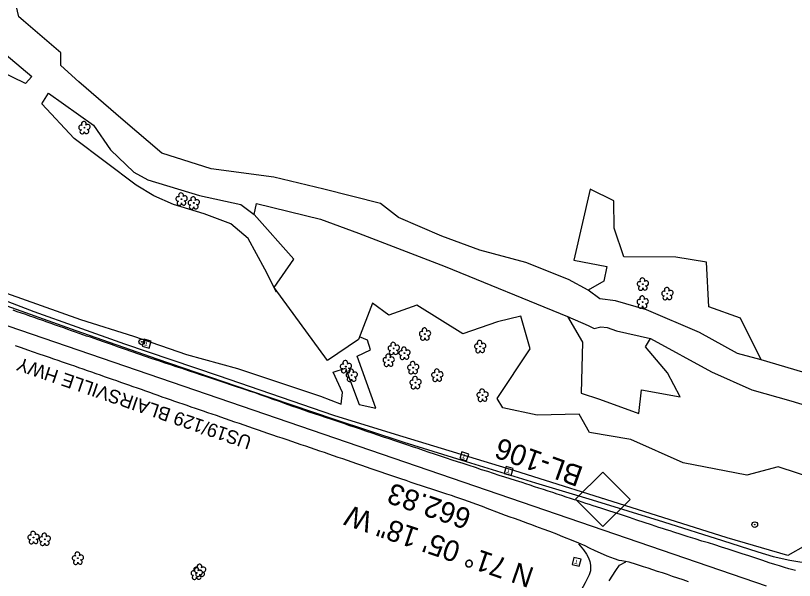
# Model space of a CAD drawing. Extents: x 478596 to 483012, y 490885 to 495165.
# Drawn here: x 479936 to 480534, y 493288 to 493722 of the extents above; entities that cross this region are included whole.
import ezdxf

# ---------------------------------------------------------------- set-up
doc = ezdxf.new("R2010")
doc.units = 0
for name, color, linetype in [('CTL Secondary Horizontal and Vertical CELL', 7, 'Continuous'), ('CTL Secondary Horizontal and Vertical Text', 7, 'Continuous'), ('Exist Guardrail', 7, 'Continuous'), ('Exist Horizontal Alignment', 7, 'Continuous'), ('Exist Horizontal Alignment Direction Label', 7, 'Continuous'), ('Exist Roads EOP', 7, 'Continuous'), ('Exist Roads EOP Text', 7, 'Continuous'), ('Exist Roads Soil', 7, 'Continuous'), ('Exist Utilities Other Located Object CELL', 7, 'Continuous'), ('Exist Utilities Telephone Pedestal CELL', 7, 'Continuous'), ('Exist Vegetation Hedge Row', 7, 'Continuous'), ('Exist Vegetation Tree CELL', 7, 'Continuous'), ('Exist Vegetation Woods Line', 7, 'Continuous')]:
    doc.layers.add(name, color=color, linetype=linetype)

msp = doc.modelspace()

# ---------------------------------------------------------------- linework, layer by layer
at = {"layer": 'CTL Secondary Horizontal and Vertical CELL'}
msp.add_line((480387.12, 493349.88), (480387.12, 493349.88), dxfattribs=at)
msp.add_lwpolyline([(480366.26, 493349.95), (480387.23, 493370.92), (480408.23, 493349.92), (480387.26, 493328.95)], close=True, dxfattribs=at)
at = {"layer": 'Exist Guardrail'}
msp.add_line((479896.1, 493510.36), (479982.05, 493479.53), dxfattribs=at)
for points in [[(479982.05, 493479.53), (480044.35, 493457.89), (480115.47, 493433.53), (480180.47, 493411.46), (480234.18, 493393.89), (480278.73, 493380.07), (480335.27, 493362.72), (480378.91, 493349.59), (480433.83, 493332.58), (480479.19, 493318.23)], [(480479.19, 493318.23), (480506.27, 493309.62), (480518.25, 493306.1), (480530.88, 493303.33), (480538.59, 493301.85), (480545.76, 493301.36), (480550.94, 493301.88), (480554.47, 493303.03), (480558.73, 493304.94), (480562.47, 493307.62), (480563, 493308.29)]]:
    msp.add_lwpolyline(points, dxfattribs=at)
at = {"layer": 'Exist Horizontal Alignment'}
msp.add_line((480512.88, 493283.24), (479885.83, 493498.07), dxfattribs=at)
at = {"layer": 'Exist Roads EOP'}
for points in [[(480535.38, 493295.14), (480530.23, 493296.67), (480526.83, 493297.64), (480523.1, 493298.73), (480519.33, 493299.91), (480515.13, 493301.28), (480510.13, 493302.95), (480504.78, 493304.72), (480499.54, 493306.41), (480494.28, 493308.09), (480488.91, 493309.84), (480483.57, 493311.58), (480478.36, 493313.26), (480473.28, 493314.87), (480468.29, 493316.4), (480463.29, 493317.92), (480458.17, 493319.48), (480452.89, 493321.11), (480447.38, 493322.86), (480441.72, 493324.68), (480438.86, 493325.61), (480435.99, 493326.54), (480433.11, 493327.48), (480430.25, 493328.42), (480424.58, 493330.29), (480418.96, 493332.16), (480413.36, 493334.03), (480407.77, 493335.9), (480402.2, 493337.75), (480396.64, 493339.58), (480391.11, 493341.38), (480385.52, 493343.17), (480379.82, 493345), (480376.93, 493345.92), (480374.06, 493346.84), (480371.19, 493347.75), (480368.32, 493348.67), (480365.38, 493349.61), (480362.29, 493350.61), (480359.04, 493351.68), (480355.64, 493352.8), (480352.15, 493353.95), (480348.64, 493355.1), (480345.1, 493356.25), (480341.54, 493357.4), (480338.02, 493358.54), (480334.6, 493359.65), (480331.28, 493360.72), (480328.05, 493361.76), (480325.02, 493362.74), (480319.88, 493364.35), (480315.78, 493365.59), (480311.71, 493366.88), (480307.48, 493368.26), (480303.12, 493369.7), (480298.63, 493371.19), (480293.99, 493372.71), (480289.21, 493374.26), (480284.43, 493375.81), (480279.71, 493377.33), (480275.33, 493378.75), (480271.26, 493380.1), (480266.92, 493381.54), (480262.3, 493383.08), (480257.85, 493384.57), (480253.6, 493386), (480249.38, 493387.42), (480245.14, 493388.87), (480240.79, 493390.36), (480236.34, 493391.89), (480231.81, 493393.42), (480227.27, 493394.93), (480222.91, 493396.36), (480218.61, 493397.75), (480213.48, 493399.45), (480210.54, 493400.44), (480205.05, 493402.29), (480200.85, 493403.71), (480197.01, 493405.01), (480192.64, 493406.49), (480188, 493408.06), (480183.34, 493409.63), (480178.67, 493411.19), (480173.98, 493412.75), (480169.48, 493414.25), (480165.36, 493415.64), (480161.37, 493417), (480157.25, 493418.41), (480152.88, 493419.92), (480148.12, 493421.58), (480143.24, 493423.3), (480138.46, 493424.99), (480133.75, 493426.67), (480129.05, 493428.38), (480124.39, 493430.07), (480119.76, 493431.67), (480115.4, 493433.14), (480113.41, 493433.8), (480109.65, 493435.01), (480105.49, 493436.38), (480100.91, 493437.92), (480096.62, 493439.36), (480092.6, 493440.72), (480088, 493442.27), (480082.72, 493444.04), (480077.1, 493445.92), (480074.18, 493446.9), (480068.59, 493448.75), (480063.67, 493450.37), (480059.22, 493451.82), (480055.05, 493453.19), (480050.74, 493454.62), (480045.87, 493456.25), (480040.73, 493457.98), (480035.62, 493459.74), (480030.51, 493461.5), (480025.37, 493463.27), (480020.15, 493465.07), (480014.77, 493466.93), (480009.37, 493468.8), (480004.09, 493470.61), (479998.74, 493472.44), (479993.13, 493474.39), (479990.26, 493475.39), (479987.38, 493476.39), (479984.51, 493477.4), (479981.63, 493478.42), (479978.72, 493479.45), (479975.73, 493480.49), (479972.66, 493481.56), (479969.51, 493482.65), (479966.32, 493483.76), (479963.1, 493484.88), (479959.85, 493486.02), (479956.57, 493487.18), (479953.28, 493488.34), (479949.98, 493489.5), (479946.69, 493490.66), (479943.39, 493491.82), (479940.13, 493492.96), (479936.94, 493494.07), (479933.81, 493495.16)], [(480453, 493286.56), (480448.93, 493287.97), (480444.86, 493289.37), (480440.85, 493290.74), (480436.9, 493292.07), (480433.01, 493293.36), (480429.2, 493294.61), (480425.51, 493295.83), (480421.93, 493297.02), (480418.48, 493298.17), (480413.04, 493299.99), (480407.4, 493301.7), (480401.76, 493302.72), (480399.73, 493303.07), (480396.02, 493304.26), (480390.59, 493306.37), (480385.33, 493308.62), (480381.25, 493310.49), (480376.92, 493312.54), (480373.59, 493314.1), (480368.64, 493316.23), (480363.19, 493318.45), (480357.69, 493320.68), (480354.64, 493321.92), (480351.76, 493323.07), (480346.51, 493325.12), (480341.32, 493327.08), (480338.54, 493328.11), (480335.62, 493329.19), (480332.57, 493330.3), (480329.41, 493331.45), (480326.13, 493332.64), (480322.73, 493333.86), (480319.27, 493335.11), (480315.83, 493336.35), (480312.4, 493337.59), (480308.98, 493338.82), (480305.75, 493340.01), (480300.38, 493342.04), (480298.24, 493342.9), (480294.71, 493344.32), (480289.58, 493346.28), (480284.54, 493348.1), (480279.48, 493349.89), (480274.17, 493351.66), (480270.8, 493352.76), (480267.14, 493353.94), (480263.39, 493355.16), (480259.54, 493356.41), (480255.6, 493357.7), (480251.63, 493359.01), (480247.66, 493360.32), (480243.71, 493361.65), (480239.77, 493362.99), (480235.85, 493364.33), (480231.95, 493365.66), (480228.08, 493366.98), (480224.23, 493368.28), (480220.41, 493369.58), (480216.62, 493370.87), (480212.87, 493372.17), (480209.14, 493373.45), (480205.44, 493374.74), (480201.76, 493376.01), (480198.1, 493377.26), (480194.46, 493378.51), (480190.85, 493379.74), (480187.26, 493380.97), (480183.69, 493382.19), (480180.14, 493383.4), (480176.6, 493384.6), (480173.05, 493385.81), (480169.5, 493387.02), (480165.95, 493388.24), (480162.39, 493389.46), (480158.81, 493390.68), (480155.22, 493391.9), (480151.61, 493393.12), (480147.99, 493394.35), (480144.36, 493395.58), (480140.71, 493396.82), (480137.05, 493398.06), (480133.38, 493399.31), (480129.7, 493400.56), (480126.02, 493401.81), (480122.32, 493403.07), (480118.64, 493404.32), (480114.97, 493405.58), (480111.34, 493406.83), (480107.73, 493408.08), (480104.15, 493409.33), (480100.59, 493410.57), (480097.06, 493411.8), (480093.55, 493413.02), (480090.1, 493414.22), (480086.73, 493415.38), (480083.44, 493416.5), (480080.24, 493417.59), (480077.07, 493418.66), (480073.9, 493419.73), (480070.72, 493420.81), (480067.54, 493421.89), (480064.36, 493422.98), (480061.17, 493424.07), (480057.99, 493425.17), (480054.8, 493426.28), (480051.62, 493427.4), (480048.44, 493428.52), (480045.26, 493429.65), (480042.09, 493430.79), (480038.91, 493431.93), (480035.71, 493433.07), (480032.49, 493434.2), (480029.25, 493435.33), (480026.02, 493436.45), (480022.81, 493437.56), (480019.64, 493438.66), (480016.49, 493439.75), (480013.35, 493440.83), (480010.22, 493441.92), (480007.1, 493443.02), (480003.99, 493444.11), (480000.84, 493445.23), (479997.61, 493446.37), (479994.3, 493447.53), (479990.92, 493448.72), (479987.54, 493449.9), (479984.25, 493451.04), (479981.06, 493452.14), (479977.96, 493453.2), (479974.87, 493454.26), (479971.71, 493455.34), (479968.46, 493456.45), (479965.14, 493457.59), (479961.65, 493458.8), (479957.87, 493460.11), (479953.8, 493461.52), (479949.46, 493463.04), (479944.93, 493464.62), (479940.28, 493466.24), (479935.53, 493467.9)]]:
    msp.add_lwpolyline(points, dxfattribs=at)
at = {"layer": 'Exist Roads Soil'}
for points in [[(480368.47, 493315.7), (480372.2, 493311.19), (480374.68, 493307.77), (480376.25, 493304.93), (480377.27, 493302.24), (480377.66, 493299.47), (480377.56, 493295.06), (480376.57, 493291.86), (480373.63, 493285.78), (480368.64, 493276.85), (480360.22, 493265.24), (480352.54, 493254.89), (480342.85, 493243.21), (480332.52, 493231.82), (480321.57, 493220.07), (480312.67, 493210.45), (480302.04, 493199.87), (480292.9, 493191.8), (480281.27, 493182.16), (480270.34, 493174.05)], [(480392.07, 493287.3), (480397.28, 493295.14), (480400.09, 493299.29), (480404.8, 493302)]]:
    msp.add_lwpolyline(points, dxfattribs=at)
at = {"layer": 'Exist Utilities Other Located Object CELL'}
for centre, radius in [((480032.68, 493470.9), 2.18), ((480032.68, 493470.9), 0.24), ((480503.95, 493330.49), 2.18), ((480503.95, 493330.49), 0.24)]:
    msp.add_circle(centre, radius, dxfattribs=at)
at = {"layer": 'Exist Utilities Telephone Pedestal CELL'}
for p, q in [((480036.45, 493469.45), (480036.45, 493469.45)), ((480280.67, 493382.91), (480280.67, 493382.91)), ((480314.82, 493371.62), (480314.82, 493371.62)), ((480367.07, 493301.9), (480367.07, 493301.9))]:
    msp.add_line(p, q, dxfattribs=at)
for points in [[(480039.88, 493471.37), (480034.53, 493472.99), (480032.9, 493467.64), (480038.25, 493466.01), (480039.88, 493471.37)], [(480284.15, 493384.73), (480278.83, 493386.49), (480277.08, 493381.18), (480282.39, 493379.42), (480284.15, 493384.73)], [(480318.23, 493373.56), (480312.87, 493375.15), (480311.28, 493369.79), (480316.64, 493368.2), (480318.23, 493373.56)], [(480370.41, 493303.97), (480364.98, 493305.35), (480363.61, 493299.92), (480369.03, 493298.55), (480370.41, 493303.97)]]:
    msp.add_lwpolyline(points, dxfattribs=at)
at = {"layer": 'Exist Vegetation Hedge Row'}
for points in [[(479912.31, 493729.75), (479912.77, 493716.89), (479923.17, 493695.39), (479948.15, 493674.84), (479943.28, 493669.47), (479923.02, 493678.95), (479883.84, 493701.77), (479859.15, 493728.66)], [(480028.35, 493591.21), (479980.57, 493627.02), (479955.9, 493653.69), (479960.94, 493662.03), (479995.41, 493637.41), (480008.48, 493618.27), (480026.45, 493601.12), (480037.28, 493595.46)], [(480037.28, 493595.46), (480076.92, 493583.19), (480108.77, 493576.45), (480119.15, 493568.71)], [(480136.16, 493509.14), (480127.35, 493526.64), (480114.4, 493550.4), (480101.18, 493561.49), (480080.52, 493569.14), (480056.96, 493576.34), (480041.9, 493583.13), (480028.35, 493591.21)], [(479982.85, 493482.21), (479949.94, 493493.89), (479898.42, 493513.77), (479891.65, 493518.15), (479898.04, 493519.04), (479985.49, 493488.15)], [(480508.77, 493457.15), (480490.82, 493462.01), (480461.46, 493478.06), (480420.69, 493495.52), (480396.94, 493502.39), (480384.86, 493503.9), (480375.77, 493510.66)], [(479985.49, 493488.15), (480026.37, 493475.35), (480067.14, 493461.19), (480106.19, 493450.33), (480170.01, 493429.21), (480186.08, 493422.99), (480187.07, 493432), (480179.88, 493447.68), (480189.41, 493450.79), (480199.73, 493422.85), (480212.53, 493419.89), (480198.26, 493460.01), (480208.49, 493464.79), (480206.21, 493472.24), (480199.94, 493474.71)], [(480359.92, 493490.4), (480375.79, 493483.36), (480380.39, 493481.05), (480385.61, 493482.46), (480390.57, 493481.98), (480397.73, 493479.32), (480423.79, 493473.35)], [(480482.8, 493320.41), (480408.96, 493343.63), (480319.51, 493371.91), (480227.63, 493399.72), (480180.38, 493414.34), (480091.64, 493444.72), (480019.72, 493469.09), (479982.85, 493482.21)], [(480597.81, 493336.9), (480588.62, 493324.24), (480576.28, 493322.48), (480547.92, 493326.91), (480542.86, 493314.56), (480529.28, 493306.77), (480482.8, 493320.41)]]:
    msp.add_lwpolyline(points, dxfattribs=at)
at = {"layer": 'Exist Vegetation Tree CELL'}
for p, q in [((479988.51, 493635.41), (479988.51, 493635.41)), ((480063.22, 493580.54), (480063.22, 493580.54)), ((480072.59, 493577.61), (480072.59, 493577.61)), ((480417.95, 493515.26), (480417.95, 493515.26)), ((480436.75, 493507.92), (480436.75, 493507.92)), ((480417.76, 493501.47), (480417.76, 493501.47)), ((480250.38, 493476.9), (480250.38, 493476.9)), ((480226.32, 493465.85), (480226.32, 493465.85)), ((480234.6, 493462.16), (480234.6, 493462.16)), ((480292.79, 493467.29), (480292.79, 493467.29)), ((480222.45, 493456.79), (480222.45, 493456.79)), ((480189.52, 493451.87), (480189.52, 493451.87)), ((480241.3, 493451.04), (480241.3, 493451.04)), ((480194.03, 493445.25), (480194.03, 493445.25)), ((480259.86, 493445.33), (480259.86, 493445.33)), ((480243.09, 493439.53), (480243.09, 493439.53)), ((480294.62, 493429.95), (480294.62, 493429.95)), ((479949.44, 493320.6), (479949.44, 493320.6)), ((479958.04, 493319.21), (479958.04, 493319.21)), ((479983.52, 493304.7), (479983.52, 493304.7)), ((480077.45, 493295.38), (480077.45, 493295.38)), ((480074.84, 493293.14), (480074.84, 493293.14))]:
    msp.add_line(p, q, dxfattribs=at)
for centre in [(479988.51, 493635.41), (480063.22, 493580.54), (480072.59, 493577.61), (480417.95, 493515.26), (480436.75, 493507.92), (480417.76, 493501.47), (480250.38, 493476.9), (480226.32, 493465.85), (480234.6, 493462.16), (480292.79, 493467.29), (480222.45, 493456.79), (480189.52, 493451.87), (480241.3, 493451.04), (480194.03, 493445.25), (480259.86, 493445.33), (480243.09, 493439.53), (480294.62, 493429.95), (479949.44, 493320.6), (479958.04, 493319.21), (479983.52, 493304.7), (480077.45, 493295.38), (480074.84, 493293.14)]:
    msp.add_circle(centre, 0.326, dxfattribs=at)
for centre, radius, start, end in [((479985.91, 493635.57), 1.73, 62.66361, 279.3457), ((479988.13, 493638.29), 1.86, 330.16508, 219.71335), ((479991.06, 493636), 1.9, 257.1011, 134.19993), ((479986.81, 493632.29), 1.69, 111.56708, 6.23104), ((479990.18, 493632.51), 1.7, 181.28216, 74.55999), ((480060.62, 493580.7), 1.73, 62.66361, 279.3457), ((480062.84, 493583.42), 1.86, 330.16508, 219.71335), ((480065.77, 493581.13), 1.9, 257.1011, 134.19993), ((480072.2, 493580.48), 1.86, 330.16508, 219.71335), ((480061.52, 493577.42), 1.69, 111.56708, 6.23104), ((480064.89, 493577.64), 1.7, 181.28216, 74.55999), ((480069.98, 493577.76), 1.73, 62.66361, 279.3457), ((480070.88, 493574.49), 1.69, 111.56708, 6.23104), ((480074.26, 493574.71), 1.7, 181.28216, 74.55999), ((480075.14, 493578.2), 1.9, 257.1011, 134.19993), ((480415.34, 493515.41), 1.73, 62.66361, 279.3457), ((480417.56, 493518.13), 1.86, 330.16508, 219.71335), ((480420.5, 493515.85), 1.9, 257.1011, 134.19993), ((480416.24, 493512.14), 1.69, 111.56708, 6.23104), ((480419.62, 493512.36), 1.7, 181.28216, 74.55999), ((480434.15, 493508.07), 1.73, 62.66361, 279.3457), ((480436.37, 493510.79), 1.86, 330.16508, 219.71335), ((480439.3, 493508.51), 1.9, 257.1011, 134.19993), ((480417.37, 493504.34), 1.86, 330.16508, 219.71335), ((480420.3, 493502.05), 1.9, 257.1011, 134.19993), ((480435.05, 493504.8), 1.69, 111.56708, 6.23104), ((480438.43, 493505.02), 1.7, 181.28216, 74.55999), ((480415.15, 493501.62), 1.73, 62.66361, 279.3457), ((480416.05, 493498.35), 1.69, 111.56708, 6.23104), ((480419.43, 493498.57), 1.7, 181.28216, 74.55999), ((480250, 493479.77), 1.86, 330.16508, 219.71335), ((480247.78, 493477.05), 1.73, 62.66361, 279.3457), ((480248.68, 493473.78), 1.69, 111.56708, 6.23104), ((480252.06, 493474), 1.7, 181.28216, 74.55999), ((480252.93, 493477.49), 1.9, 257.1011, 134.19993), ((480223.72, 493466), 1.73, 62.66361, 279.3457), ((480225.94, 493468.72), 1.86, 330.16508, 219.71335), ((480228.87, 493466.44), 1.9, 257.1011, 134.19993), ((480290.18, 493467.45), 1.73, 62.66361, 279.3457), ((480292.4, 493470.17), 1.86, 330.16508, 219.71335), ((480295.34, 493467.88), 1.9, 257.1011, 134.19993), ((480224.62, 493462.73), 1.69, 111.56708, 6.23104), ((480228, 493462.95), 1.7, 181.28216, 74.55999), ((480231.99, 493462.31), 1.73, 62.66361, 279.3457), ((480234.21, 493465.03), 1.86, 330.16508, 219.71335), ((480237.15, 493462.74), 1.9, 257.1011, 134.19993), ((480291.08, 493464.17), 1.69, 111.56708, 6.23104), ((480294.46, 493464.39), 1.7, 181.28216, 74.55999), ((480189.13, 493454.75), 1.86, 330.16508, 219.71335), ((480219.84, 493456.95), 1.73, 62.66361, 279.3457), ((480222.06, 493459.67), 1.86, 330.16508, 219.71335), ((480225, 493457.38), 1.9, 257.1011, 134.19993), ((480232.89, 493459.03), 1.69, 111.56708, 6.23104), ((480236.27, 493459.26), 1.7, 181.28216, 74.55999), ((480240.91, 493453.92), 1.86, 330.16508, 219.71335), ((480186.91, 493452.03), 1.73, 62.66361, 279.3457), ((480187.81, 493448.75), 1.69, 111.56708, 6.23104), ((480191.19, 493448.98), 1.7, 181.28216, 74.55999), ((480192.07, 493452.46), 1.9, 257.1011, 134.19993), ((480193.64, 493448.12), 1.86, 330.16508, 219.71335), ((480220.75, 493453.67), 1.69, 111.56708, 6.23104), ((480224.12, 493453.89), 1.7, 181.28216, 74.55999), ((480238.69, 493451.2), 1.73, 62.66361, 279.3457), ((480242.97, 493448.14), 1.7, 181.28216, 74.55999), ((480243.85, 493451.63), 1.9, 257.1011, 134.19993), ((480259.48, 493448.2), 1.86, 330.16508, 219.71335), ((480191.42, 493445.4), 1.73, 62.66361, 279.3457), ((480195.7, 493442.35), 1.7, 181.28216, 74.55999), ((480196.58, 493445.84), 1.9, 257.1011, 134.19993), ((480239.59, 493447.92), 1.69, 111.56708, 6.23104), ((480242.7, 493442.41), 1.86, 330.16508, 219.71335), ((480257.25, 493445.49), 1.73, 62.66361, 279.3457), ((480258.16, 493442.21), 1.69, 111.56708, 6.23104), ((480261.53, 493442.43), 1.7, 181.28216, 74.55999), ((480262.41, 493445.92), 1.9, 257.1011, 134.19993), ((480192.32, 493442.13), 1.69, 111.56708, 6.23104), ((480240.48, 493439.69), 1.73, 62.66361, 279.3457), ((480241.38, 493436.41), 1.69, 111.56708, 6.23104), ((480244.76, 493436.63), 1.7, 181.28216, 74.55999), ((480245.64, 493440.12), 1.9, 257.1011, 134.19993), ((480292.01, 493430.1), 1.73, 62.66361, 279.3457), ((480294.23, 493432.82), 1.86, 330.16508, 219.71335), ((480297.17, 493430.54), 1.9, 257.1011, 134.19993), ((480292.91, 493426.83), 1.69, 111.56708, 6.23104), ((480296.29, 493427.05), 1.7, 181.28216, 74.55999), ((479949.05, 493323.47), 1.86, 330.16508, 219.71335), ((479946.83, 493320.75), 1.73, 62.66361, 279.3457), ((479947.73, 493317.48), 1.69, 111.56708, 6.23104), ((479951.11, 493317.7), 1.7, 181.28216, 74.55999), ((479951.99, 493321.19), 1.9, 257.1011, 134.19993), ((479955.44, 493319.36), 1.73, 62.66361, 279.3457), ((479957.66, 493322.08), 1.86, 330.16508, 219.71335), ((479960.59, 493319.8), 1.9, 257.1011, 134.19993), ((479956.34, 493316.09), 1.69, 111.56708, 6.23104), ((479959.72, 493316.31), 1.7, 181.28216, 74.55999), ((479980.92, 493304.85), 1.73, 62.66361, 279.3457), ((479983.14, 493307.57), 1.86, 330.16508, 219.71335), ((479986.07, 493305.29), 1.9, 257.1011, 134.19993), ((479981.82, 493301.58), 1.69, 111.56708, 6.23104), ((479985.2, 493301.8), 1.7, 181.28216, 74.55999), ((480077.06, 493298.25), 1.86, 330.16508, 219.71335), ((480072.24, 493293.29), 1.73, 62.66361, 279.3457), ((480074.46, 493296.01), 1.86, 330.16508, 219.71335), ((480074.84, 493295.53), 1.73, 62.66361, 279.3457), ((480077.39, 493293.73), 1.9, 257.1011, 134.19993), ((480079.12, 493292.48), 1.7, 181.28216, 74.55999), ((480079.99, 493295.97), 1.9, 257.1011, 134.19993), ((480073.14, 493290.02), 1.69, 111.56708, 6.23104), ((480075.74, 493292.26), 1.69, 111.56708, 6.23104), ((480076.52, 493290.24), 1.7, 181.28216, 74.55999)]:
    msp.add_arc(centre, radius, start, end, dxfattribs=at)
at = {"layer": 'Exist Vegetation Woods Line'}
for points in [[(480048.01, 493615.8), (480018.32, 493641.12), (479984.19, 493670.57), (479970.31, 493683.23), (479970.5, 493692.92), (479938.15, 493720.67), (479933.77, 493739.13), (479914.48, 493763.64), (479909.91, 493765.97)], [(480540.92, 493447.58), (480508.77, 493457.15), (480492.94, 493489.07), (480468.63, 493497.9), (480466.93, 493532.21), (480443.4, 493535.98), (480403.26, 493536.26), (480395.84, 493558.28), (480395.61, 493579.26), (480377.51, 493588.16), (480364.74, 493533.56), (480390.2, 493528.75), (480387.9, 493517.6), (480375.77, 493510.66), (480360.76, 493518.67), (480327.98, 493531.78), (480292.49, 493541.26), (480263.38, 493552.08), (480230.03, 493566.38), (480216.33, 493577.07), (480172.54, 493588.25), (480134.14, 493597.38), (480085.92, 493603.82), (480048.01, 493615.8)], [(480497.76, 493368.38), (480448.93, 493377.96), (480408.69, 493395.89), (480376.78, 493401.15), (480368.85, 493415.4), (480336.76, 493414.49), (480310.19, 493420.26), (480305.87, 493427.51), (480331.4, 493465.44), (480324.16, 493490.53), (480306.15, 493486.34), (480279.41, 493476.94), (480244.06, 493499.15), (480222.57, 493491.34), (480210.09, 493500.6), (480199.19, 493472.8), (480175.55, 493456.59), (480134.39, 493512.53), (480149.51, 493534.4), (480119.15, 493568.71), (480120.75, 493577.28), (480169.99, 493565.01), (480199.4, 493554.45), (480266, 493528.69), (480359.92, 493490.4), (480371.59, 493470.74), (480370.4, 493431.51), (480384.53, 493426.99), (480414.84, 493415.97), (480416.89, 493434.05), (480446.51, 493428.55), (480436.9, 493447.09), (480420.06, 493467.1), (480423.79, 493473.35), (480470.83, 493447.97), (480501.74, 493433.99), (480531.73, 493425.48)], [(480531.73, 493425.48), (480588.15, 493408.52), (480661.3, 493378.45), (480690.58, 493367.38), (480676.64, 493360.9), (480648.74, 493370.46), (480623.68, 493361.76), (480597.81, 493336.9), (480555.54, 493350.81), (480550.98, 493365.48), (480522.06, 493374.82), (480497.76, 493368.38)]]:
    msp.add_lwpolyline(points, dxfattribs=at)

# ---------------------------------------------------------------- texts
at = {"layer": 'CTL Secondary Horizontal and Vertical Text'}
msp.add_text('BL-106', height=16, rotation=160.33976, dxfattribs=at).set_placement((480373.08, 493374.35))
at = {"layer": 'Exist Horizontal Alignment Direction Label'}
for s, p in [('662.83', (480287.11, 493341.55)), ('N 71%%d 05\' 18" W', (480335.3, 493296.82))]:
    msp.add_text(s, height=16, rotation=161.08844, dxfattribs=at).set_placement(p)
at = {"layer": 'Exist Roads EOP Text'}
msp.add_text('US19/129 BLAIRSVILLE HWY', height=10.4, rotation=161.08833, dxfattribs=at).set_placement((480117.97, 493397.87))
at = {"layer": 'Exist Utilities Telephone Pedestal CELL'}
for rotation, p in [(163.1168, (480038.03, 493470.76)), (161.70033, (480282.28, 493384.18)), (163.50554, (480316.39, 493372.95)), (165.74806, (480368.59, 493303.28))]:
    msp.add_text('T', height=3.42, rotation=rotation, dxfattribs=at).set_placement(p)

doc.saveas('drawing.dxf')
